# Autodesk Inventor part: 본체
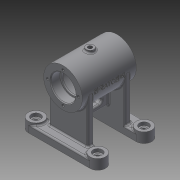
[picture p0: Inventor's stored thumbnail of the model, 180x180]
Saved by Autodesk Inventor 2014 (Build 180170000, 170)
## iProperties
Created: 2015-11
Part Number: 본체
Material: 일반
Document SubType Name: Modeling
Designer: basic
Density: 1 g/cm^3
Appearance: 기본값
Author: basic
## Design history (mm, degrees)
sketch "스케치1"
  geometry: C1 r 25 at (0, 0); 1 further point
  constraints: 1 centre point, 1 coincident
  dimensions: "d0" = 50 diameter of C1
extrude "돌출1" new body sketch "스케치1" stored distance "d1" = 70; taper "d2" = 0 deg
sketch "스케치2"
  geometry: C1 r 25 at (0, 0) reference; C2 r 16 at (0, 0)
  constraints: 1 centre point, 1 coincident
  dimensions: "d3" = 32 diameter of C2
extrude "돌출2" cut sketch "스케치2" distance "d4" = 12; taper "d5" = 0 deg
sketch "스케치3"
  geometry: C1 r 21 at (0, 0); 1 further point
  constraints: 1 centre point, 1 coincident
  dimensions: "d6" = 42 diameter of C1
extrude "돌출3" cut sketch "스케치3" stored distance "d7" = 42; taper "d8" = 0 deg
sketch "스케치4"
  geometry: C1 r 16 at (0, 0) reference; C2 r 14 at (0, 0)
  constraints: 1 centre point, 1 coincident
  dimensions: "d9" = 28 diameter of C2
extrude "돌출4" cut sketch "스케치4" stored distance "d10" = 42; taper "d11" = 0 deg
node "작업 평면1"
sketch "스케치5"
  geometry: L1 (-40, -30)-(40, -30); L2 (-40, -20)-(40, -20); L3 (40, -40)-(-40, -40); A1 r 10 centre (-40, -30) between (-40, -20) and (-40, -40); A2 r 10 centre (40, -30) between (40, -40) and (40, -20); 3 further points
  constraints: 8 end point, 4 point on circle, 4 tangent, 2 centre point, 2 midpoint, 1 horizontal, 1 parallel, 1 vertical alignment
  dimensions: "d13" = 80 distance of L1.start L1.end; "d14" = 20 distance between parallel lines of L2 L3; "d15" = 40 distance from line of point (0, 0) L3
extrude "돌출5" join sketch "스케치5" distance "d16" = 10; taper "d17" = 0 deg
sketch "스케치6"
  geometry: L1 (40, -20)-(-40, -20) reference; L2 (-25, -20)-(25, -20); L3 (25, -20)-(25, -28); L4 (25, -28)-(-25, -28); L5 (-25, -28)-(-25, -20); 2 further points
  constraints: 8 end point, 2 midpoint, 2 parallel, 1 horizontal, 1 perpendicular
  dimensions: "d18" = 8 distance between parallel lines of L4 L2; "d19" = 50 distance of L3.end L4.end
extrude "돌출6" join sketch "스케치6" stored distance "d20" = 10; taper "d21" = 0 deg
sketch "스케치7"
  geometry: C1 r 10 at (40, -30); A1 r 10 centre (-40, -30) between (-40, -20) and (-40, -40) reference; A2 r 10 centre (40, -30) between (40, -40) and (40, -20) reference; 2 further points
  constraints: 2 coincident, 1 centre point, 1 concentric, 1 vertical alignment, 2 other
extrude "돌출7" join sketch "스케치7" distance "d22" = 3; taper "d23" = 0 deg
sketch "스케치8"
  geometry: C1 r 10 at (0, 0) reference; 2 further points
  constraints: 1 coincident
hole "구멍1" sketch "스케치8" at (0, 0) diameter "d24" = 6; stored, may be unused: countersink angle "d28" = 90 deg, drill point angle "d30" = 118 deg; dims "d25" = 6, "d26" = 12, "d27" = 4, "d29" = 8
node "작업 평면3"
  node "작업 평면2"
sketch "스케치9"
  geometry: L1 (25, 28)-(25, 20) reference; L2 (25, 20)-(-25, 20) reference; L3 (-25, 20)-(-25, 28) reference; L4 (-25, 28)-(25, 28) reference; L5 (25, -20)-(25, -28) reference; L6 (25, -28)-(-25, -28) reference; L7 (-25, -28)-(-25, -20) reference; L8 (-25, -20)-(25, -20) reference; L9 (4, -20)-(-4, -20); L10 (-4, -20)-(-4, 20); L11 (-4, 20)-(4, 20); L12 (4, 20)-(4, -20); 3 further points
  constraints: 8 end point, 4 midpoint, 2 parallel, 1 horizontal, 1 perpendicular
  dimensions: "d32" = 8 distance between parallel lines of L10 L12
extrude "돌출8" join sketch "스케치9" stored distance "d33" = 3; taper "d34" = 0 deg
sketch "스케치10"
  geometry: L1 (-20.322, 0)-(-20.322, 40) reference; L2 (-10, 12)-(-10, 28); L3 (-13.5, 12)-(-13.5, 28); L4 (-6.5, 28)-(-6.5, 12); L5 (23, 60)-(23, 40) reference; A1 r 3.5 centre (-10, 12) between (-13.5, 12) and (-6.5, 12); A2 r 3.5 centre (-10, 28) between (-6.5, 28) and (-13.5, 28); 2 further points
  constraints: 8 end point, 4 point on circle, 4 tangent, 2 centre point, 2 parallel, 1 horizontal alignment, 1 midpoint
  dimensions: "d35" = 33 distance from line of L5 point (-10, 20); "d36" = 3.5 radius of A2; "d37" = 23 dimension on A2 A1
extrude "돌출9" cut sketch "스케치10" stored distance "d38" = 3; taper "d39" = 0 deg
sketch "스케치11"
  geometry: C1 r 16 at (0, 0) reference; 1 further point
  constraints: 1 horizontal alignment
  dimensions: "d40" = 20 distance of C1.centre point (20, 0)
hole "구멍2" sketch "스케치11" at (20, 0) diameter "d41" = 3.242; stored, may be unused: countersink angle "d45" = 90 deg, drill point angle "d47" = 118 deg; dims "d42" = 8, "d43" = 12, "d44" = 4, "d46" = 10
node "작업 평면4"
sketch "스케치12"
  geometry: C1 r 5 at (0, 0); 1 further point
  constraints: 1 centre point, 1 coincident
  dimensions: "d52" = 10 diameter of C1
extrude "돌출10" join sketch "스케치12" stored distance "d53" = 3; taper "d54" = 0 deg
sketch "스케치13"
  geometry: C1 r 5 at (0, 0) reference; 1 further point
  constraints: 1 coincident
hole "구멍3" sketch "스케치13" at (0, 0) diameter "d55" = 5.188; stored, may be unused: countersink angle "d59" = 90 deg, drill point angle "d61" = 118 deg; dims "d56" = 10, "d57" = 12, "d58" = 4, "d60" = 10
sketch "스케치14"
  geometry: L1 (0, 0)-(0, -14); L2 (0, 0)-(-12.5, 21.651); A1 r 25 centre (0, 0) between (-4, 24.678) and (-25, 0) reference; 1 further point
  constraints: 4 end point, 1 point on circle, 1 vertical, 1 vertical alignment, 1 other
  dimensions: "d65" = 30 deg angle of L2 L1
node "작업 평면6"
  node "작업 평면5"
sketch "스케치15"
  geometry: C1 r 6 at (0, 0); 1 further point
  constraints: 1 centre point, 1 coincident
  dimensions: "d67" = 12 diameter of C1
extrude "돌출11" join sketch "스케치15" stored distance "d68" = 3; taper "d69" = 0 deg
sketch "스케치16"
  geometry: C1 r 6 at (0, 0) reference; 1 further point
  constraints: 1 coincident
hole "구멍4" sketch "스케치16" at (0, 0) diameter "d70" = 5.188; stored, may be unused: countersink angle "d74" = 90 deg, drill point angle "d76" = 118 deg; dims "d71" = 10, "d72" = 12, "d73" = 4, "d75" = 10
fillet "모깎기1" dims "d77" = 3
fillet "모깎기2" dims "d78" = 2
fillet "모깎기3" dims "d79" = 0.3
fillet "모깎기4" dims "d80" = 2
fillet "모깎기5" dims "d81" = 2
fillet "모깎기6" dims "d82" = 2
fillet "모깎기7" dims "d83" = 2
fillet "모깎기8" dims "d84" = 2
fillet "모깎기9" dims "d85" = 2
fillet "모깎기10" dims "d86" = 2
fillet "모깎기11" dims "d87" = 2
chamfer "모따기1" distance "d88" = 1; stored, may be unused: second distance "d89" = 2, angle "d90" = 45 deg
chamfer "모따기2" distance "d91" = 1; stored, may be unused: second distance "d92" = 2, angle "d93" = 45 deg
node "작업 평면7"
sketch "스케치17"
  geometry: L1 (35, -25)-(35, 25) reference; L2 (35, -25)-(-35, -25) reference; 2 further points
  constraints: 1 other
  dimensions: "d95" = 35 distance from line of point (0, 0) L1; "d96" = 25 distance from line of point (0, 0) L2
feature "엠보싱1" sketch "스케치17" dims "d3" = 32, "d97" = 0.5, "d98" = 0
fillet "모깎기12" dims "d99" = 2
chamfer "모따기3" distance "d100" = 1; stored, may be unused: second distance "d101" = 2, angle "d102" = 45 deg
chamfer "모따기4" distance "d103" = 1; stored, may be unused: second distance "d104" = 2, angle "d105" = 45 deg
chamfer "모따기5" distance "d106" = 1; stored, may be unused: second distance "d107" = 2, angle "d108" = 45 deg
chamfer "모따기6" distance "d109" = 1; stored, may be unused: second distance "d110" = 2, angle "d111" = 45 deg
fillet "모깎기13" dims "d112" = 0.3
node "솔리드1"
mirror "대칭1"
mirror "대칭2"
mirror "대칭3"
pattern_circular "원형 패턴1" dims angle "d49" = 360 deg
mirror "대칭4"
node "절단 모서리 투영1"
other parameters: "d12" = 68, "d51" = -28, "d66" = 3, "d94" = -25
